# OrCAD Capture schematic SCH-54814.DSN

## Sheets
1 01 Title Page: title: PNEV7642MA; rev: A1; company: NXP Semiconductors; note: SCH-54814 PDF: SPF-54814; note: 6501 William Cannon Drive West; note: Austin, TX 78735-8598
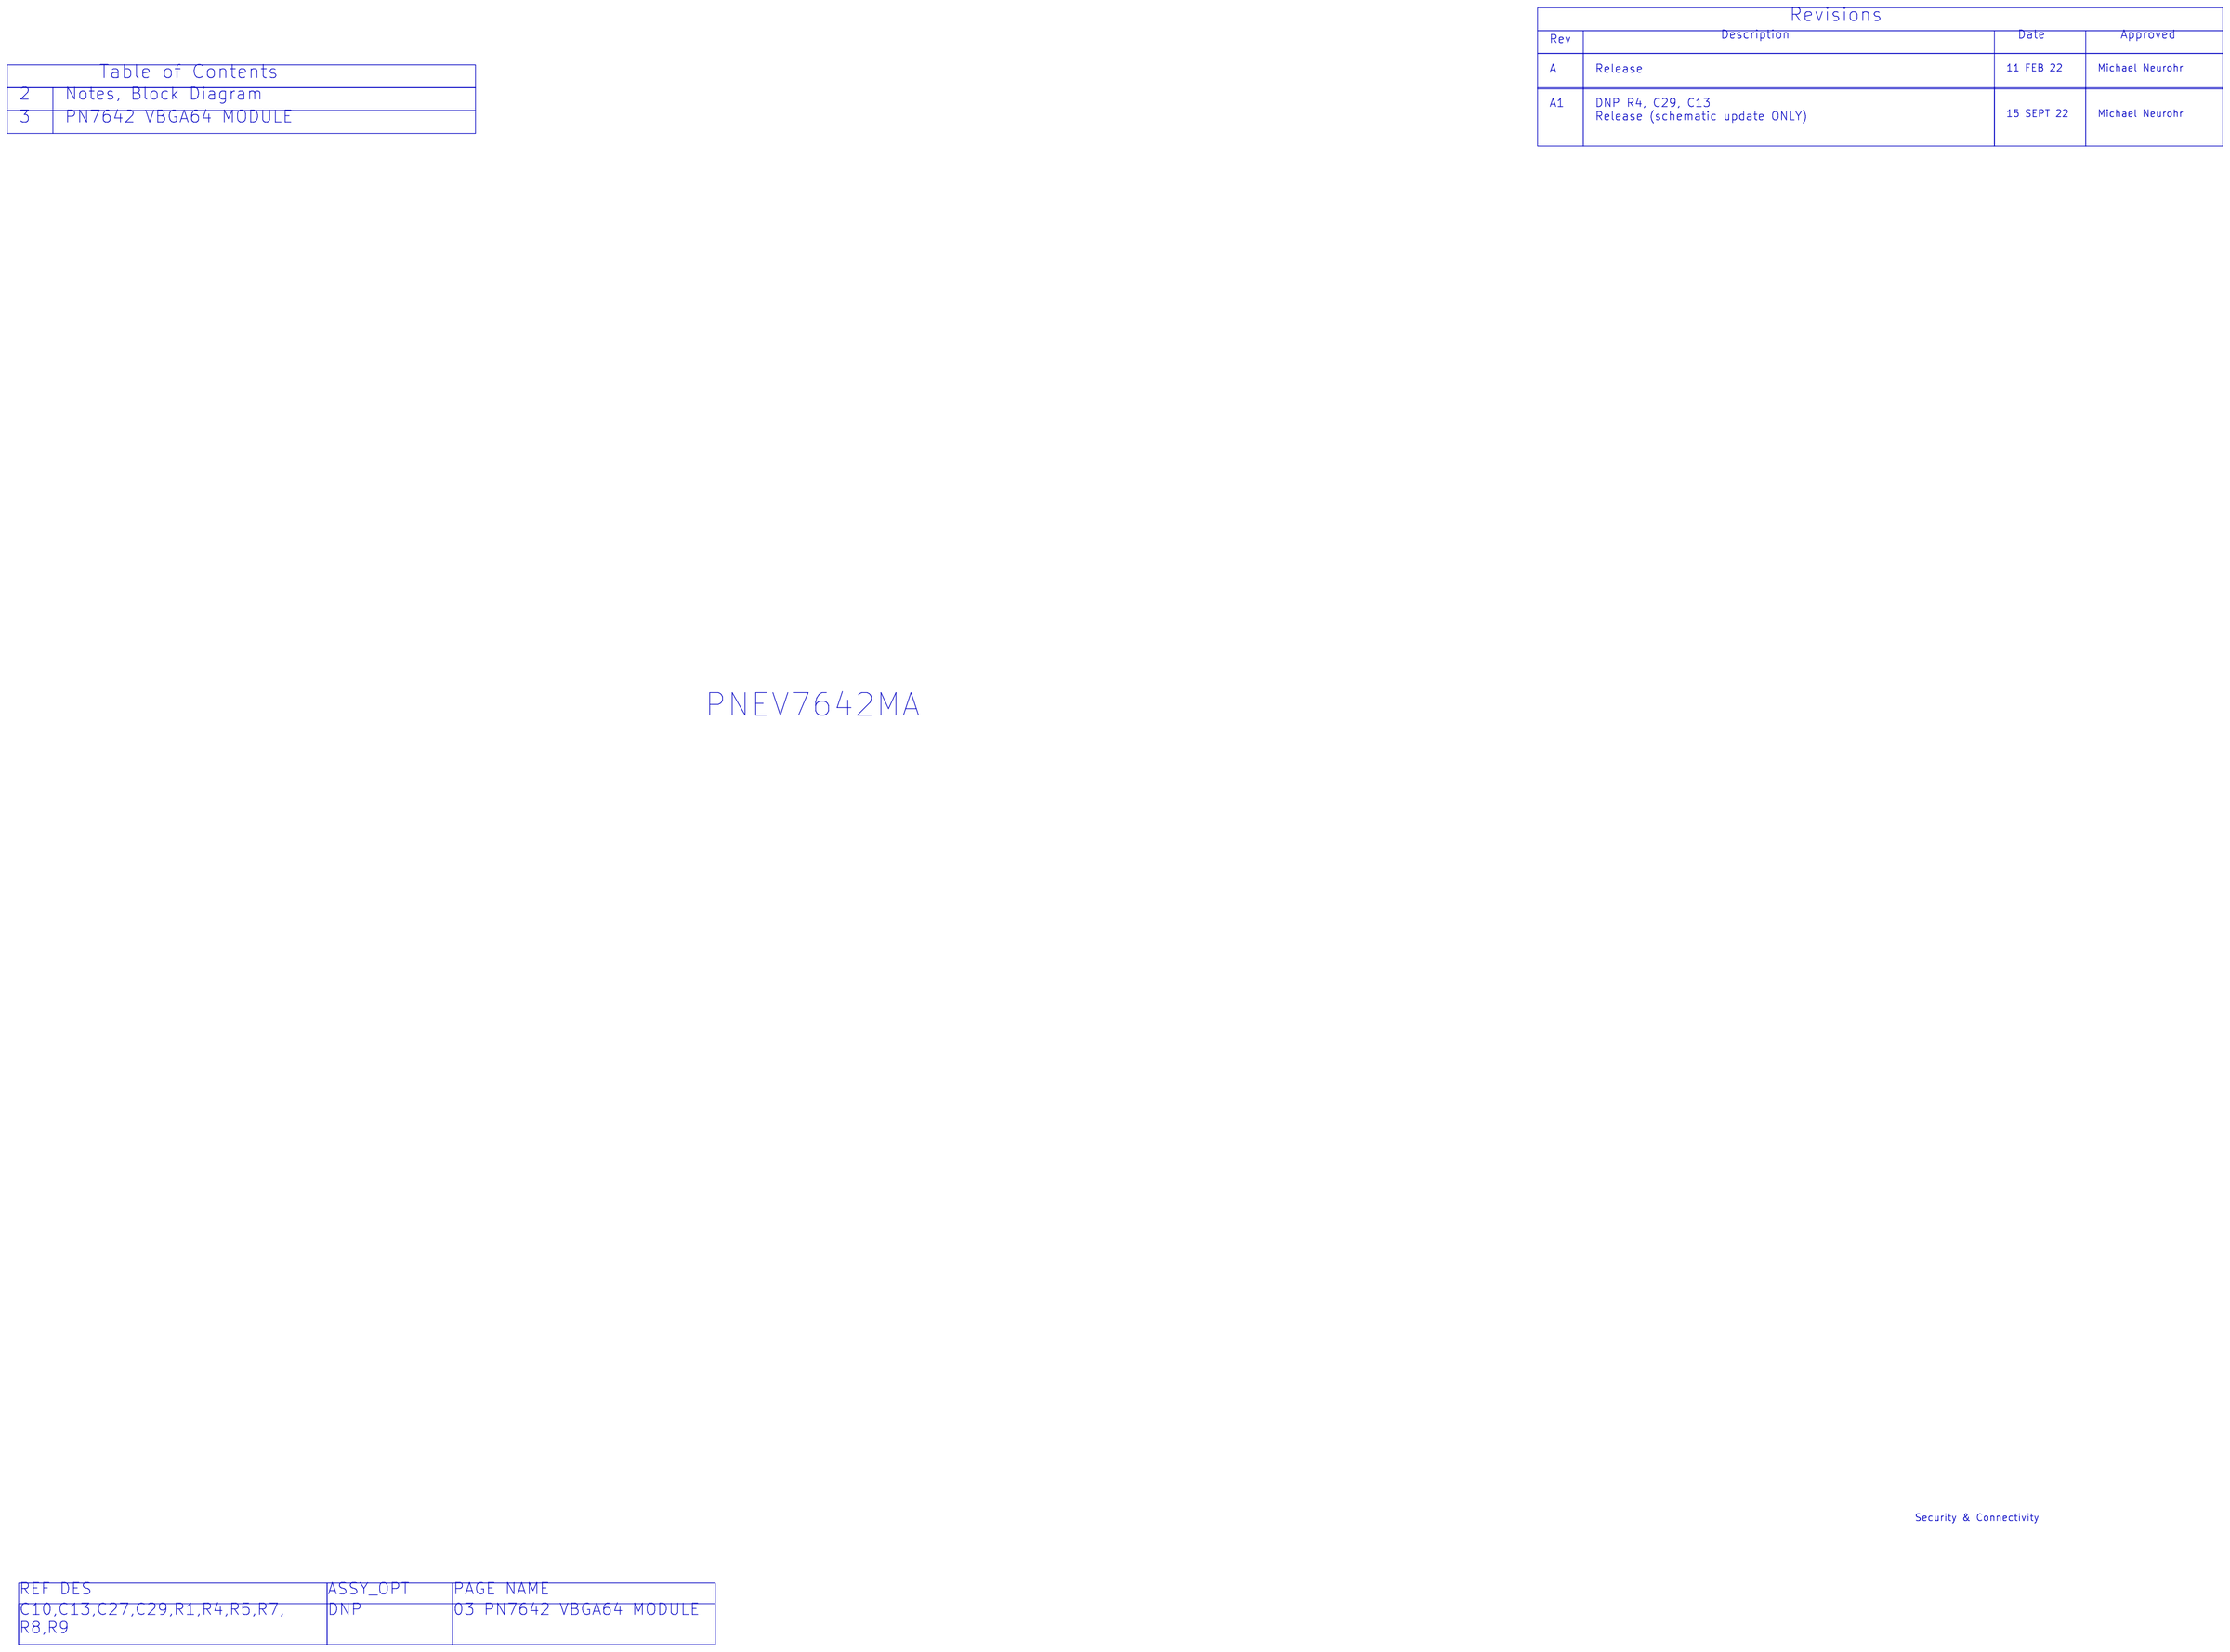
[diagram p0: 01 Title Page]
2 02 Notes, Block Diagram
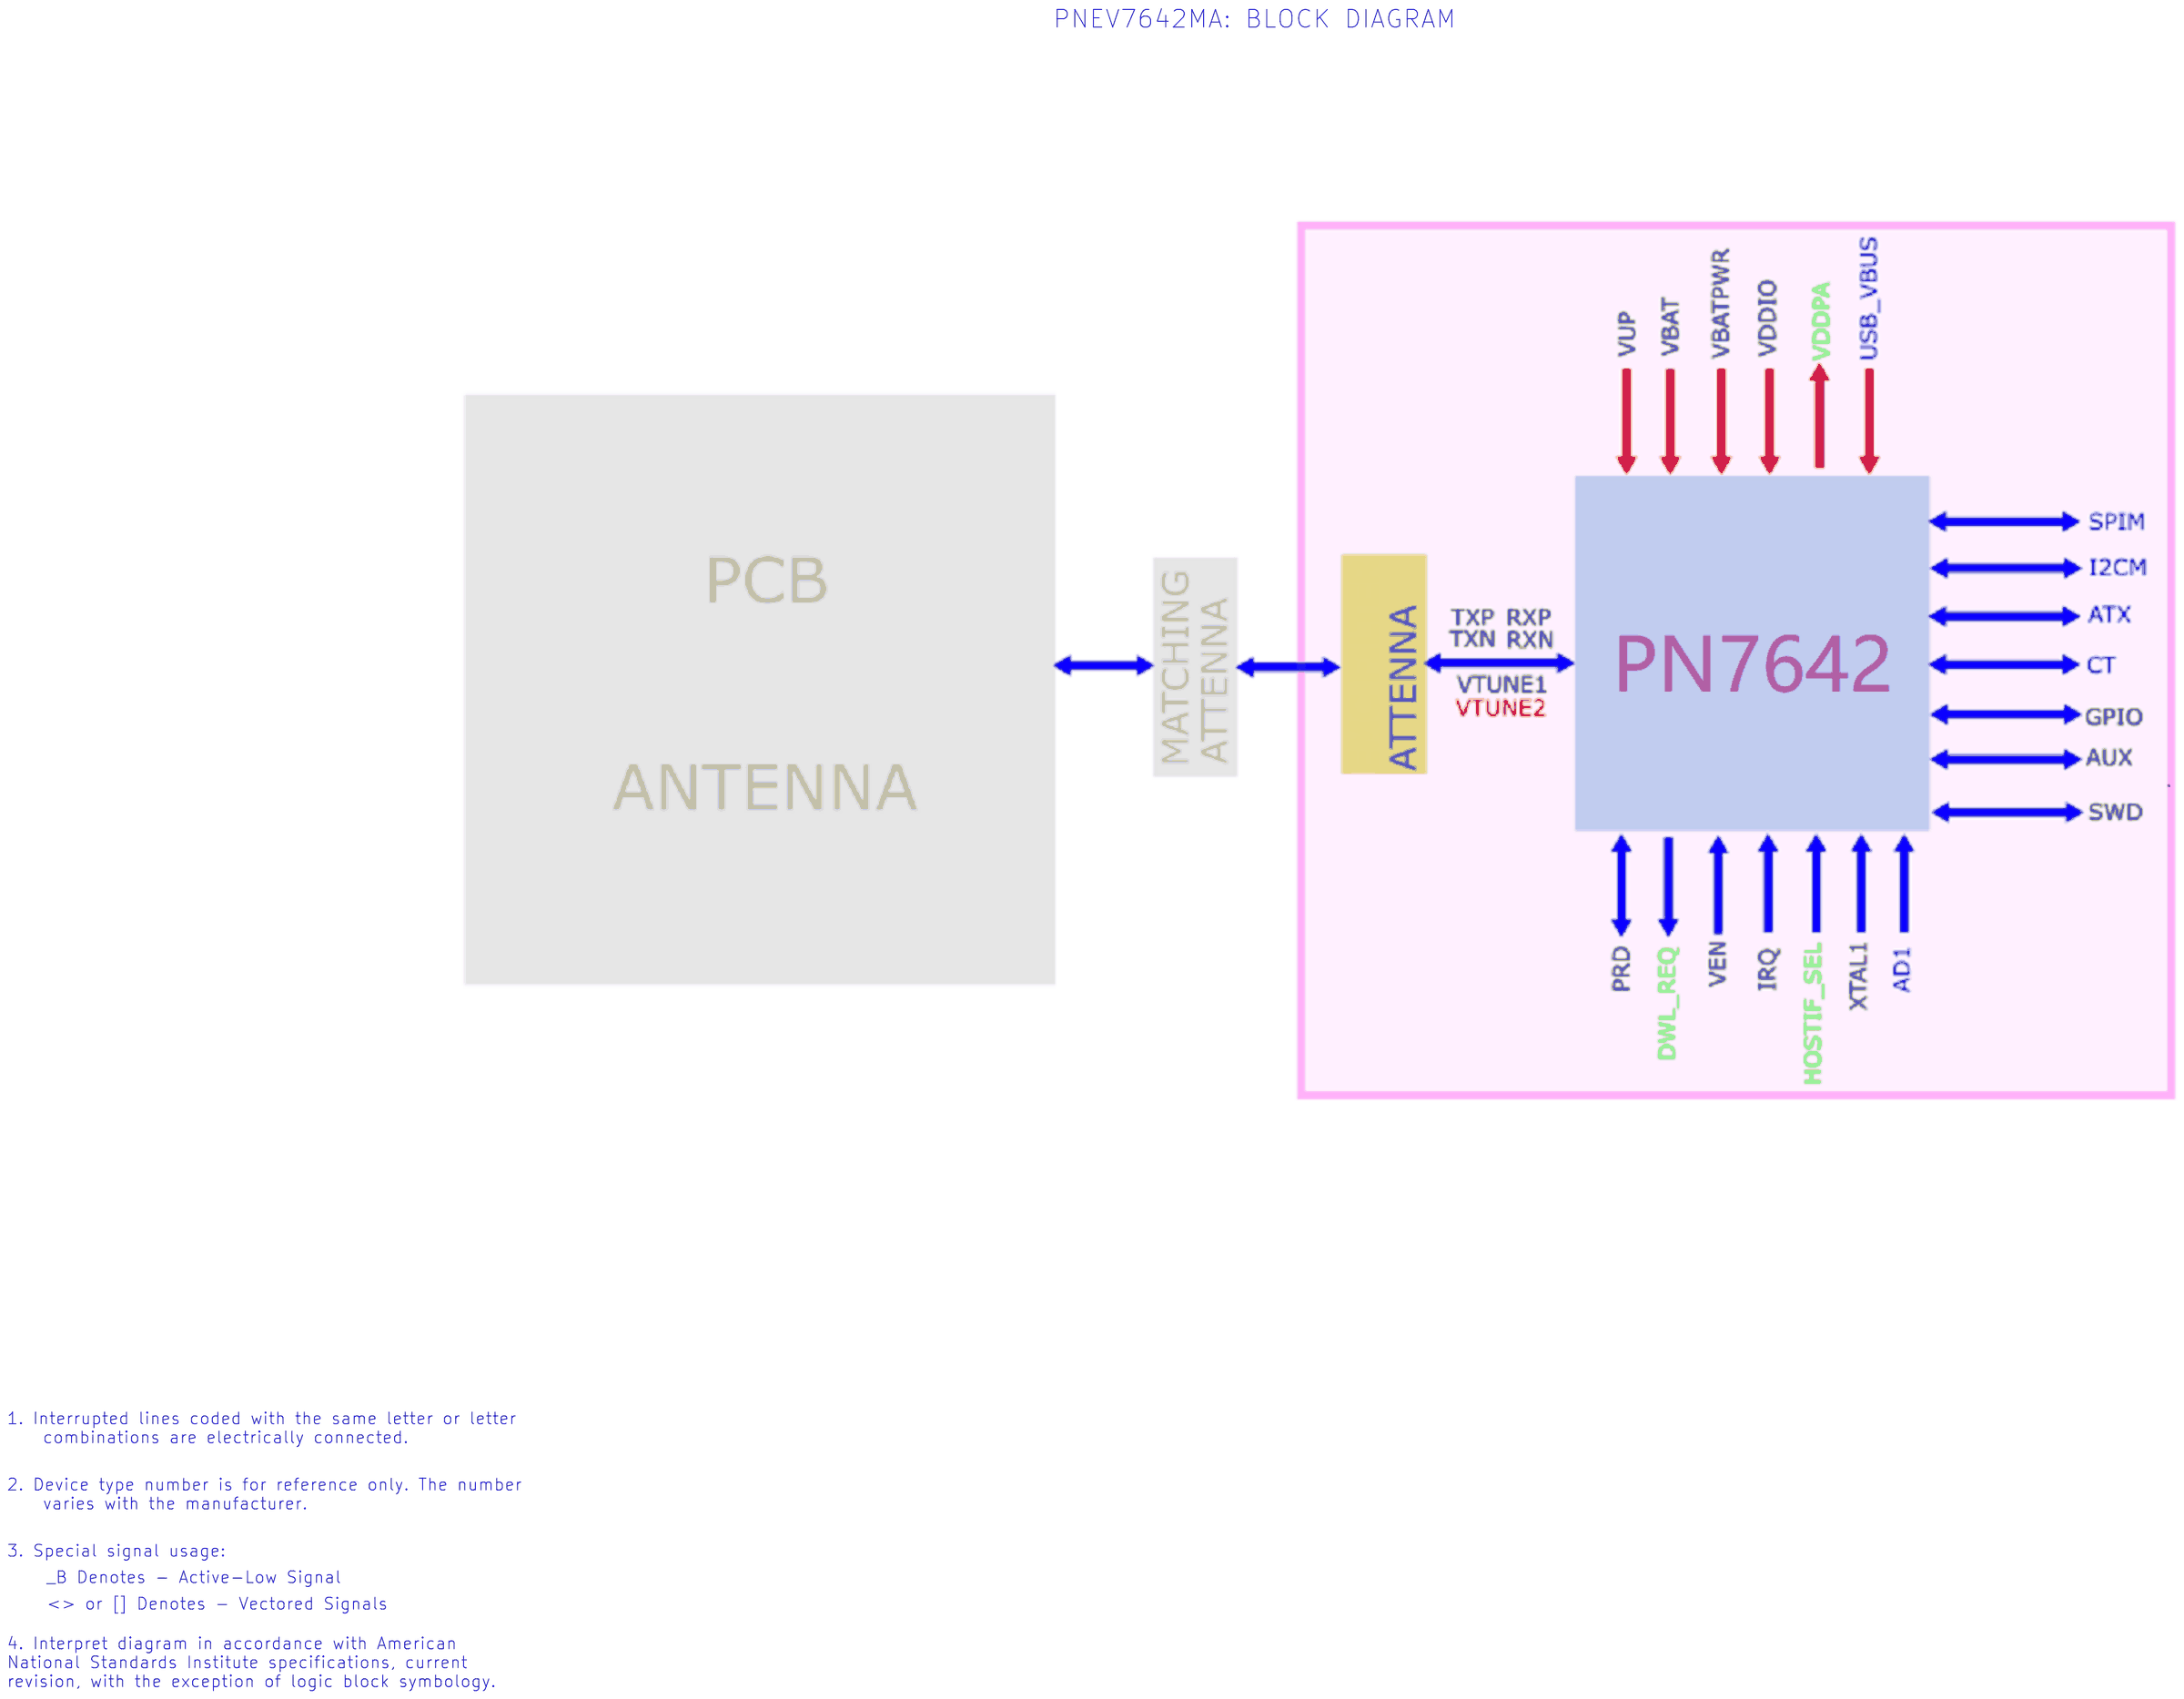
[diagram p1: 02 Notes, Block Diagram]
3 03 PN7642 VBGA64 MODULE: size C
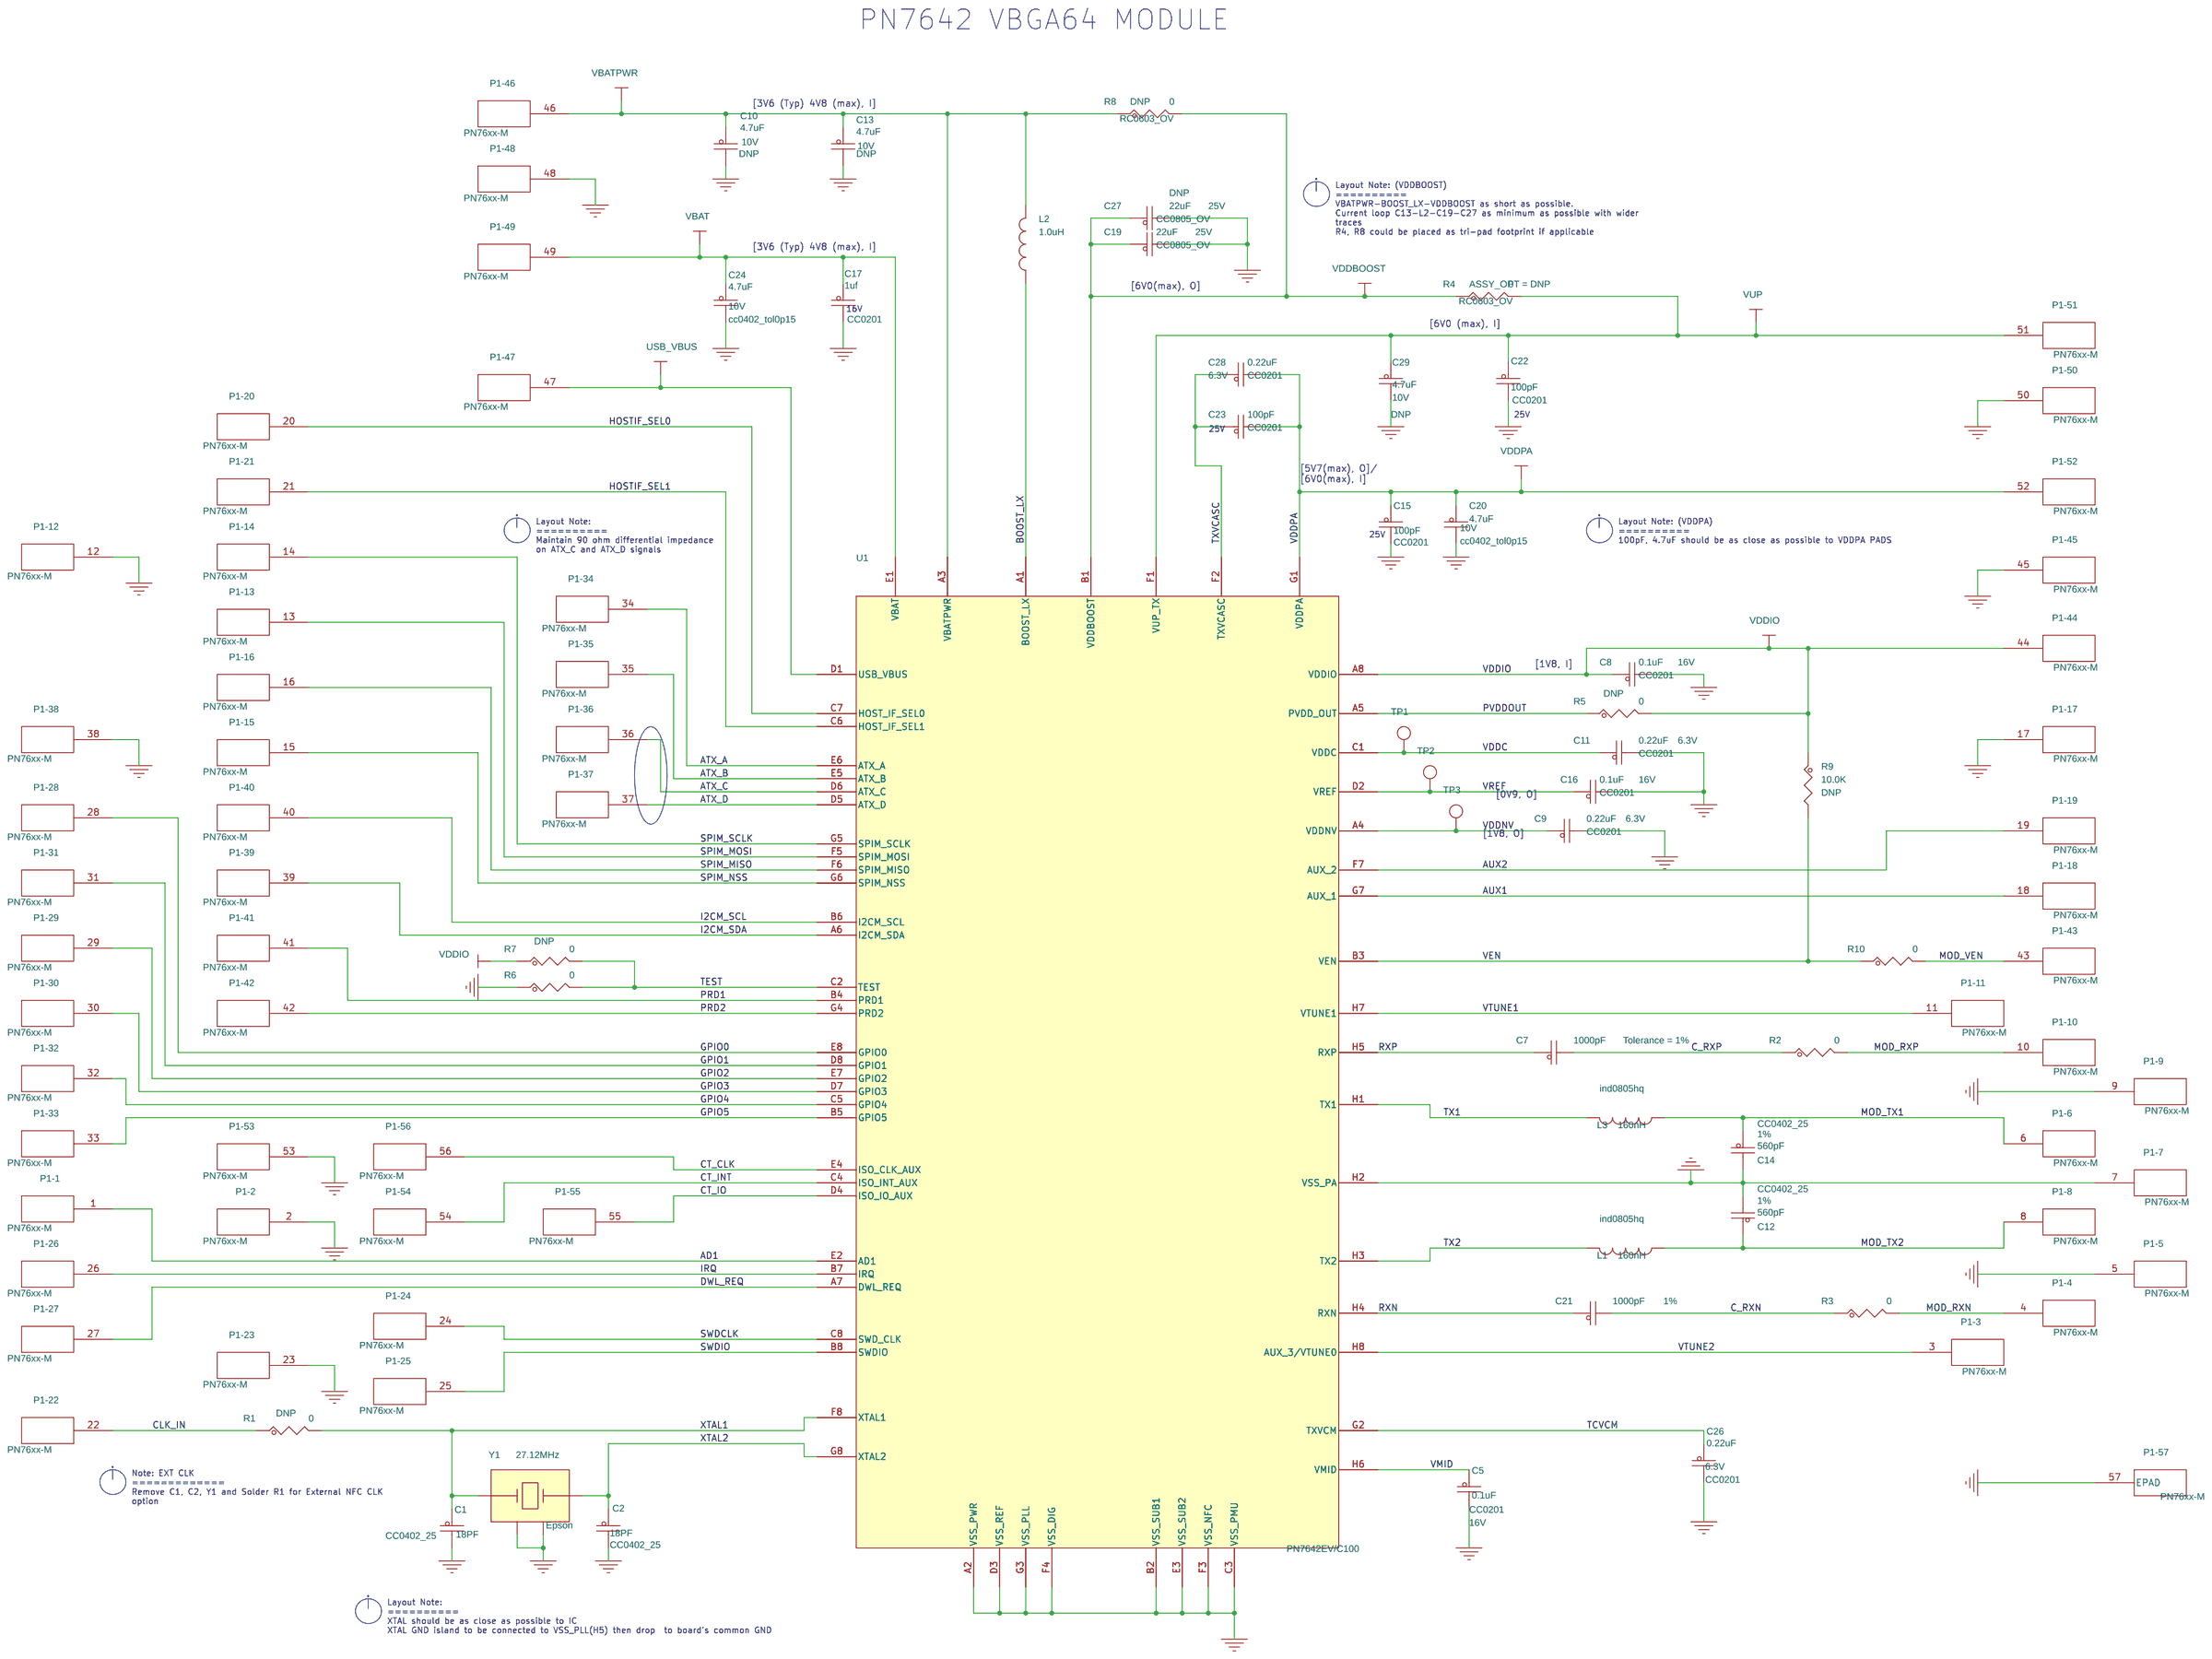
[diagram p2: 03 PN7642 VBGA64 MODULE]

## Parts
C1  18PF  [CC0402_25]
C2  18PF  [CC0402_25]
C5  0.1uF  [CC0201]
C7  1000pF  [CC0402_25]
C8  0.1uF  [CC0201]
C9  0.22uF  [CC0201]
C10  4.7uF  [cc0402_tol0p15]
C11  0.22uF  [CC0201]
C12  560pF  [CC0402_25]
C13  4.7uF  [cc0402_tol0p15]
C14  560pF  [CC0402_25]
C15  100pF  [CC0201]
C16  0.1uF  [CC0201]
C17  1uf  [CC0201]
C19  22uF  [CC0805_OV]
C20  4.7uF  [cc0402_tol0p15]
C21  1000pF  [CC0402_25]
C22  100pF  [CC0201]
C23  100pF  [CC0201]
C24  4.7uF  [cc0402_tol0p15]
C26  0.22uF  [CC0201]
C27  22uF  [CC0805_OV]
C28  0.22uF  [CC0201]
C29  4.7uF  [cc0402_tol0p15]
L1  160nH  [ind0805hq]
L2  1.0uH  [ind_1008_smd]
L3  160nH  [ind0805hq]
P1  PN76xx-M  [module56_1p52_25x25mm]  (sections -1,-10,-11,-12,-13,-14,-15,-16,-17,-18,-19,-2,-20,-21,-22,-23,-24,-25,-26,-27,-28,-29,-3,-30,-31,-32,-33,-34,-35,-36,-37,-38,-39,-4,-40,-41,-42,-43,-44,-45,-46,-47,-48,-49,-5,-50,-51,-52,-53,-54,-55,-56,-57,-6,-7,-8,-9)
R1  0  [RC0402_25]
R2  0  [RC0402_25]
R3  0  [RC0402_25]
R4  0  [RC0603_OV]
R5  0  [RC0402_25]
R6  0  [RC0402_25]
R7  0  [RC0402_25]
R8  0  [RC0603_OV]
R9  10.0K  [RC0402_25]
R10  0  [RC0402_25]
TP1  TPAD_040  [TPAD_040]
TP2  TPAD_040  [TPAD_040]
TP3  TPAD_040  [TPAD_040]
U1  PN7642EV/C100  [vfbga64_0p5_4p6x4p6]
Y1  27.12MHz  [xtal4_1p6x1p2]

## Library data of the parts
C1 C2 = CAP_NP: CAP CER 18PF 50V 1% C0G 0402; AGILE_PN: 150-76630; CAD_APPROVED: Yes; FPLIST: CC0402_25,CC0402_HD,0402_CC; HEIGHT: 0.59MM; MFG_NAME01: YAGEO; MFG_PN01: CC0402FRNPO9BN180; ROHS: Yes; Rated Voltage: 50V; Temp Range: -55C to +125C; Tolerance: 1%; VOLTAGE: 50V
C5 C8 C16 = CAP_NP: CAP CER 0.1uF 16V 10% X5R 0201; AGILE_PN: 150-80059; CAD_APPROVED: Yes; FPLIST: CC0201,CC0201_HD,0201_CC; HEIGHT: 0.33MM; MFG_NAME01: MURATA; MFG_PN01: GRM033R61C104KE14D; Package Size: 0201; ROHS: Yes; Rated Voltage: 16V; Temp Range: -55C to +85C; Temp_Range: -55 to +85°C; Tolerance: 10%; VOLTAGE: 16V
C7 C21 = CAP_NP: CAP CER 1000pF 50V 1% C0G 0402; AGILE_PN: 150-80735; CAD_APPROVED: Yes; FPLIST: CC0402_25,CC0402_HD,0402_CC; HEIGHT: 0.55MM; MFG_NAME01: KEMET; MFG_PN01: C0402C102F5GEC7411; Package Size: 0402 (1005 Metric); Package Type: SMD; ROHS: Yes; Rated Voltage: 50V; Temp Range: -55C to +125C; Tolerance: 1%; VOLTAGE: 50V
C9 C11 C26 C28 = CAP_NP: CAP CER 0.22uF 6.3V 10% X5R 0201; AGILE_PN: 150-79474; CAD_APPROVED: Yes; FPLIST: CC0201,CC0201_HD,0201_CC,cc_0201_cir; HEIGHT: 0.33MM; MFG_NAME01: MURATA; MFG_PN01: GRM033R60J224KE15D; Package Size: 0201; Package Type: Paper Tape; ROHS: Yes; Rated Voltage: 6.3V; Temp Range: -55C to +85C; Tolerance: 10%; VOLTAGE: 6.3V
C10 C13 C29 = CAP_NP: CAP CER 4.7uF 10V 10% X5R 0402_WIDE; AGILE_PN: 150-79778; ASSY_OPT: DNP; CAD_APPROVED: Yes; FPLIST: CC0402_25,CC0402_HD,0402_CC; HEIGHT: 0.65MM; MFG_NAME01: TDK; MFG_PN01: C1005X5R1A475K050BC; Package Size: 0402; ROHS: Yes; Rated Voltage: 10V; Temp Range: -55C to +85C; Tolerance: 10%; VOLTAGE: 10V
C12 C14 = CAP_NP: CAP CER 560pF 50V 1% C0G AEC-Q200 0402; AGILE_PN: 150-80601; CAD_APPROVED: Yes; FPLIST: CC0402_25,CC0402_HD,0402_CC; HEIGHT: 0.55MM; MFG_NAME01: MURATA; MFG_PN01: GCM1555C1H561FA16D; Package Size: 0402; Package Type: SMT; ROHS: Yes; Rated Voltage: 50V; Temp Range: -55C to +125C; Temp_Range: -55C to +125C; Tolerance: 1%; VOLTAGE: 50V
C15 C22 C23 = CAP_NP: CAP CER 100PF 25V 5% COG CC0201; AGILE_PN: 150-75742; CAD_APPROVED: Yes; FPLIST: CC0201,CC0201_HD,0201_CC; HEIGHT: 0.33 MM; MFG_NAME01: SAMSUNG; MFG_PN01: CL03C101JA3NNNC; ROHS: Yes; Rated Voltage: 25V; Temp Range: -55C to +125C; Tolerance: 5%
C17 = CAP_NP: CAP CER 1uF 16V 20% X5R 0201; AGILE_PN: 150-79855; CAD_APPROVED: Yes; FPLIST: CC0201,CC0201_HD,0201_CC,cc_0201_cir; HEIGHT: 0.39MM; MFG_NAME01: SAMSUNG; MFG_PN01: CL03A105MO3NRNH; Package Size: 0201; Package Type: Cardboard Type, 7" reel; ROHS: Yes; Rated Voltage: 16V; Temp Range: -55C to +85C; Tolerance: 20%
C19 = CAP_NP: CAP CER 22uF 25V 20% X5R 0805; AGILE_PN: 150-79304; CAD_APPROVED: Yes; FPLIST: CC0805_OV,CC0805,0805_CC; HEIGHT: 1.45MM; MFG_NAME01: MURATA; MFG_PN01: GRM21BR61E226ME44; Package Size: 0805; Package Type: SMD; ROHS: Yes; Rated Voltage: 25V; Temp Range: -55C to +85C; Tolerance: 20%; VOLTAGE: 25V
C20 C24 = CAP_NP: CAP CER 4.7uF 10V 10% X5R 0402_WIDE; AGILE_PN: 150-79778; CAD_APPROVED: Yes; FPLIST: CC0402_25,CC0402_HD,0402_CC; HEIGHT: 0.65MM; MFG_NAME01: TDK; MFG_PN01: C1005X5R1A475K050BC; Package Size: 0402; ROHS: Yes; Rated Voltage: 10V; Temp Range: -55C to +85C; Tolerance: 10%; VOLTAGE: 10V
C27 = CAP_NP: CAP CER 22uF 25V 20% X5R 0805; AGILE_PN: 150-79304; ASSY_OPT: DNP; CAD_APPROVED: Yes; FPLIST: CC0805_OV,CC0805,0805_CC; HEIGHT: 1.45MM; MFG_NAME01: MURATA; MFG_PN01: GRM21BR61E226ME44; Package Size: 0805; Package Type: SMD; ROHS: Yes; Rated Voltage: 25V; Temp Range: -55C to +85C; Tolerance: 20%; VOLTAGE: 25V
L1 L3 = INDUCTOR: IND PWR 160nH@100MHZ 930mA 2% 0805; AGILE_PN: 180-78936; CAD_APPROVED: Yes; HEIGHT: 1.52MM; MFG_NAME01: MURATA; MFG_PN01: LQW2BANR16G00L; PART_TYPE: INDUCTOR\0603; ROHS: Yes; TOL: 5%; Temp Range: -55° C to + 125° C; Temp_Range: -40C to +85C
L2 = INDUCTOR: IND PWR 1.0UH@1MHZ 1.6A 20% 1008; AGILE_PN: 180-77657; CAD_APPROVED: Yes; HEIGHT: 1MM; MFG_NAME01: MURATA; MFG_PN01: LQM2HPN1R0MG0L; PART_TYPE: INDUCTOR\POWER; ROHS: Yes; TOL: 20%; Temp Range: -55°C to +125°C; Tolerance: 20%
P1 = TP_RECT_56P_EP: NFC MODULE TRITON LGA81 4X56 60MIL 25MMX25MM NO PART TO ORDER; AGILE_PN: TMP-CIP-6400; CAD_APPROVED: Yes; HEIGHT: 2.35MM; MFG_NAME01: NXP SEMICONDUCTORS; MFG_PN01: (NO PART TO ORDER); PRE_APN: 510-78452; ROHS: Yes
R1 R5 R7 = RES: RES MF ZERO OHM 1/16W 5% 0402; AGILE_PN: 470-75394; ASSY_OPT: DNP; CAD_APPROVED: Yes; FPLIST: RC0402_25,RC0402_HD,RC0402_X2,0402_CC; HEIGHT: 0.45 MM; MFG_NAME01: YAGEO AMERICA; MFG_PN01: RC0402JR-070RL; ROHS: Yes; Tolerance: 5%; VOLTAGE: 1/16W
R2 R3 R6 R10 = RES: RES MF ZERO OHM 1/16W 5% 0402; AGILE_PN: 470-75394; CAD_APPROVED: Yes; FPLIST: RC0402_25,RC0402_HD,RC0402_X2,0402_CC; HEIGHT: 0.45 MM; MFG_NAME01: YAGEO AMERICA; MFG_PN01: RC0402JR-070RL; ROHS: Yes; Tolerance: 5%; VOLTAGE: 1/16W
R4 R8 = RES: RES MF ZERO OHM 1/10W -- AEC-Q200 0603; AGILE_PN: 470-75407; ASSY_OPT: DNP; CAD_APPROVED: Yes; FPLIST: RC0603_OV,RC0603,R603-X2,0603_CC,r0603_sj_nsp; HEIGHT: 0.6MM; MFG_NAME01: PANASONIC; MFG_PN01: ERJ-3GEY0R00V; ROHS: Yes; Temp Range: –55 °C to +155 °C; Tolerance: 1%; VOLTAGE: 1/10W
R9 = RES: RES MF 10.0K 1/16W 1% AEC-Q200 0402; AGILE_PN: 470-75416; ASSY_OPT: DNP; CAD_APPROVED: Yes; FPLIST: RC0402_25,RC0402_HD,0402_CC; HEIGHT: 0.4MM; MFG_NAME01: KOA SPEER; MFG_PN01: RK73H1ETTP1002F; ROHS: Yes; SIGNAL_MODEL: DEFAULT_RESISTOR_10000OHM_2_1; TOL: 5%; Temp Range: –55 °C to +155 °C; Tolerance: 1%
TP1-TP3 = TESTLOOP: TEST POINT PAD 40MIL DIA SMT, NO PART TO ORDER; AGILE_PN: 211-76643; CAD_APPROVED: Yes; HEIGHT: 0.1MM; MFG_NAME01: NOTACOMPONENT; MFG_PN01: NOTACOMPONENT; ROHS: Yes
U1 = PN7640EV_BGA64: IC MCU ARM CORTEX M33 W/ NFC 256KB FLASH 32KB RAM 90MHz 1.62-3.6V VFBGA64; 3D_Mechanical_Footprint_File: http://fcl.am.freescale.net/ALLEGRO/step/vfbga64_0p5_4p6x4p6.step; AGILE_PN: 344-02557; CAD_APPROVED: Yes; HEIGHT: 0.9 MM; MFG_NAME01: NXP SEMICONDUCTORS; ROHS: Yes; Temp Range: -40 to +85C
Y1 = XTAL_13: XTAL 27.12MHz 30PPM 10pF SMD; AGILE_PN: 230-78084; CAD_APPROVED: Yes; HEIGHT: 0.35MM; MFG_NAME01: Epson; MFG_PN01: FA-118T 27.1200MD50Z-K3; ROHS: Yes

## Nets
GND: C1.2 C2.2 C5.2 C8.2 C9.2 C10.2 C11.2 C12.2 C13.2 C14.2 C15.2 C16.2 C17.2 C19.2 C20.2 C22.2 C24.2 C26.2 C27.2 C29.2 P1.2 P1.5 P1.7 P1.9 P1.12 P1.17 P1.23 P1.38 P1.45 P1.48 P1.50 P1.53 P1.57(EPAD) R6.1 U1.A2(VSS_PWR) U1.B2(VSS_SUB1) U1.C3(VSS_PMU) U1.D3(VSS_REF) U1.E3(VSS_SUB2) U1.F3(VSS_NFC) U1.F4(VSS_DIG) U1.G3(VSS_PLL) U1.H2(VSS_PA) Y1.2 Y1.4
PVDDOUT: R5.1 U1.A5(PVDD_OUT)
VBAT: C17.1 C24.1 P1.49 U1.E1(VBAT)
VBATPWR: C10.1 C13.1 L2.2 P1.46 R8.1 U1.A3(VBATPWR)
VDDBOOST: C19.1 C27.1 R4.1 R8.2 U1.B1(VDDBOOST)
VDDC: C11.1 TP1.1(Pin1) U1.C1(VDDC)
VDDIO: C8.1 P1.44 R5.2 R7.1 R9.1 U1.A8(VDDIO)
VDDNV: C9.1 TP3.1(Pin1) U1.A4(VDDNV)
VDDPA: C15.1 C20.1 C23.2 C28.2 P1.52 U1.G1(VDDPA)
AD1: P1.1 U1.E2(AD1)
ATX_A: P1.34 U1.E6(ATX_A)
ATX_B: P1.35 U1.E5(ATX_B)
ATX_C: P1.36 U1.D6(ATX_C)
ATX_D: P1.37 U1.D5(ATX_D)
AUX1: P1.18 U1.G7(AUX_1)
AUX2: P1.19 U1.F7(AUX_2)
BOOST_LX: L2.1 U1.A1(BOOST_LX)
C_RXN: C21.2 R3.1
C_RXP: C7.2 R2.1
CLK_IN: P1.22 R1.1
CT_CLK: P1.56 U1.E4(ISO_CLK_AUX)
CT_INT: P1.54 U1.C4(ISO_INT_AUX)
CT_IO: P1.55 U1.D4(ISO_IO_AUX)
DWL_REQ: P1.27 U1.A7(DWL_REQ)
GPIO0: P1.28 U1.E8(GPIO0)
GPIO1: P1.31 U1.D8(GPIO1)
GPIO2: P1.29 U1.E7(GPIO2)
GPIO3: P1.30 U1.D7(GPIO3)
GPIO4: P1.32 U1.C5(GPIO4)
GPIO5: P1.33 U1.B5(GPIO5)
HOSTIF_SEL0: P1.20 U1.C7(HOST_IF_SEL0)
HOSTIF_SEL1: P1.21 U1.C6(HOST_IF_SEL1)
I2CM_SCL: P1.40 U1.B6(I2CM_SCL)
I2CM_SDA: P1.39 U1.A6(I2CM_SDA)
IRQ: P1.26 U1.B7(IRQ)
MOD_RXN: P1.4 R3.2
MOD_RXP: P1.10 R2.2
MOD_TX1: C14.1 L3.2 P1.6
MOD_TX2: C12.1 L1.2 P1.8
MOD_VEN: P1.43 R10.2
PRD1: P1.41 U1.B4(PRD1)
PRD2: P1.42 U1.G4(PRD2)
RXN: C21.1 U1.H4(RXN)
RXP: C7.1 U1.H5(RXP)
SPIM_MISO: P1.16 U1.F6(SPIM_MISO)
SPIM_MOSI: P1.13 U1.F5(SPIM_MOSI)
SPIM_NSS: P1.15 U1.G6(SPIM_NSS)
SPIM_SCLK: P1.14 U1.G5(SPIM_SCLK)
SWDCLK: P1.24 U1.C8(SWD_CLK)
SWDIO: P1.25 U1.B8(SWDIO)
TCVCM: C26.1 U1.G2(TXVCM)
TEST: R6.2 R7.2 U1.C2(TEST)
TX1: L3.1 U1.H1(TX1)
TX2: L1.1 U1.H3(TX2)
TXVCASC: C23.1 C28.1 U1.F2(TXVCASC)
USB_VBUS: P1.47 U1.D1(USB_VBUS)
VEN: R9.2 R10.1 U1.B3(VEN)
VMID: C5.1 U1.H6(VMID)
VREF: C16.1 TP2.1(Pin1) U1.D2(VREF)
VTUNE1: P1.11 U1.H7(VTUNE1)
VTUNE2: P1.3 U1.H8(AUX_3/VTUNE0)
VUP: C22.1 C29.1 P1.51 R4.2 U1.F1(VUP_TX)
XTAL1: C1.1 R1.2 U1.F8(XTAL1) Y1.1
XTAL2: C2.1 U1.G8(XTAL2) Y1.3

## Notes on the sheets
sheet 1
- Revisions
- Rev
- Description
- Date
- Approved
- Table of Contents
- A
- Release
- 11 FEB 22
- Michael Neurohr
- 2
- Notes, Block Diagram
- A1
- DNP R4, C29, C13
  Release (schematic update ONLY)
- 3
- PN7642 VBGA64 MODULE
- 15 SEPT 22
- Michael Neurohr
- PNEV7642MA
- Security & Connectivity
- REF DES
- ASSY_OPT
- PAGE NAME
- C10,C13,C27,C29,R1,R4,R5,R7,
  R8,R9
- DNP
- 03 PN7642 VBGA64 MODULE
sheet 2
- PNEV7642MA: BLOCK DIAGRAM
- 1. Interrupted lines coded with the same letter or letter
      combinations are electrically connected.
- 2. Device type number is for reference only. The number
      varies with the manufacturer.
- 3. Special signal usage:
- _B Denotes - Active-Low Signal
- <> or [] Denotes - Vectored Signals
- 4. Interpret diagram in accordance with American
  National Standards Institute specifications, current
  revision, with the exception of logic block symbology.
sheet 3
- PN7642 VBGA64 MODULE
- [3V6 (Typ) 4V8 (max), I]
- i
- Layout Note: (VDDBOOST)
  ==========
  VBATPWR-BOOST_LX-VDDBOOST as short as possible.
  Current loop C13-L2-C19-C27 as minimum as possible with wider
  traces
  R4, R8 could be placed as tri-pad footprint if applicable
- [3V6 (Typ) 4V8 (max), I]
- [6V0(max), O]
- 16V
- [6V0 (max), I]
- 25V
- 25V
- [5V7(max), O]/
  [6V0(max), I]
- i
- Layout Note:
  ==========
  Maintain 90 ohm differential impedance
  on ATX_C and ATX_D signals
- i
- Layout Note: (VDDPA)
  ==========
  100pF, 4.7uF should be as close as possible to VDDPA PADS
- 25V
- [1V8, I]
- [0V9, O]
- [1V8, O]
- i
- Note: EXT CLK
  =============
  Remove C1, C2, Y1 and Solder R1 for External NFC CLK
  option
- i
- Layout Note:
  ==========
  XTAL should be as close as possible to IC
  XTAL GND island to be connected to VSS_PLL(H5) then drop  to board's common GND
